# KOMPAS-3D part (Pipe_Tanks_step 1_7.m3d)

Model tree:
1. X Axis
2. Y Axis
3. Z Axis  (labels: T-Bend Dn 50; Pipe Dn 50; Bend 90 Dn 50; C:\Program Files\ASCON\KOMPAS-3D V10\Sys\graphic.lyt)
     Òîëùèíà ñòåíêè 1 = 1

Referenced files in C:\Documents and Settings\kashirsky\Мои документы\Camtasia Studio\Pipelines3D\Tanks\: Tanks_step 1.a3d, Tanks_step 1.spw
Referenced files in C:\Documents and Settings\kashirsky\Мои документы\Camtasia Studio\Pipelines3D\Tanks\Tanks_step 1_Pipes\: Pipe_Tanks_step 1_7.m3d
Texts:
  Pipe Dn 50
  Steel ASTM A295
  Three Point Plane
  Plane at Angle
  Line and Point Plane
  Axis through Two Vertices
  Axis of Feature
  Axis of Conical Surface
  Axis through Edge
  Trim by Surface
  Trim by Sketch
  Feature with No History
  Intersection Axis of Two Planes
  Two Line Plane
  Line and Face Plane
  Bend by line
  Hole in sheet body
  Cut in sheet body
  Point in CM
  Linear Dimension from Line to Point
  Surface Finish Symbol
  Geometric Tolerance Symbol
  Leader #1
  Leader #2
  Leader #3
  Shape Deviations and Datum
  Node point number
  Mark of coordination axis
  Node point designation
  Mark/Reference designation with leader
  Mark/reference designation on line
  Mark/Reference designation without leader
  T-Bend Dn 50
  Bend 90 Dn 50
  Plane of section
